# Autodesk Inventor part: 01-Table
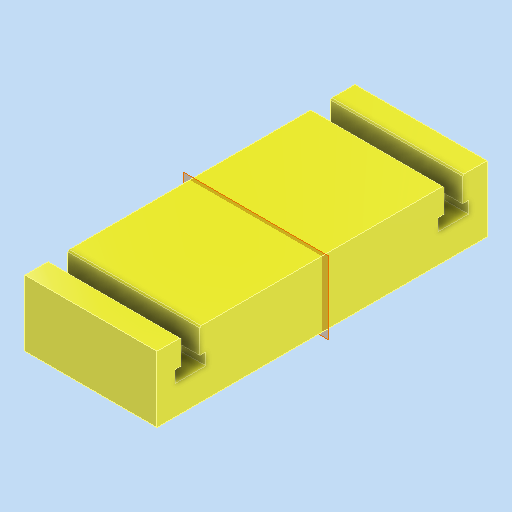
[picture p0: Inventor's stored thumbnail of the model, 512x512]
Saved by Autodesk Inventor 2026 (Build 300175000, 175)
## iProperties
Created: 2025-12
Part Number: 01-Table
Material: Générique
Document SubType Name: Modeling
Designer: thierry.jost
Density: 1 g/cm^3
Appearance: Jaune
Author: thierry.jost
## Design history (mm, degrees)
sketch "Esquisse1"
  geometry: L1 (25.468, 125)-(-24.532, 125); L2 (-24.532, 125)-(-24.532, -125); L3 (-24.532, -125)-(25.468, -125); L4 (25.468, -125)-(25.468, 125); 1 further point
  constraints: 8 end point, 2 parallel, 1 horizontal, 1 perpendicular
  dimensions: "d0" = 250 distance of L3.end L1.start; "d1" = 50 distance of L1.start L1.end; "d13" = 125 distance from line of L1 point (0, 0) (= 0.5 x d0)
extrude "Extrusion1" new body sketch "Esquisse1" distance "d2" = 100; taper "d3" = 0 deg
sketch "Esquisse2"
  geometry: L1 (-88, 6.468)-(-88, -2.532); L2 (-88, -2.532)-(-111, -2.532); L3 (-111, -2.532)-(-111, 6.468); L4 (-106.5, 58.725)-(-92.5, 58.725); L5 (-92.5, 58.725)-(-92.5, 6.468); L6 (-106.5, 6.468)-(-106.5, 58.725); L7 (-111, 6.468)-(-106.5, 6.468); L8 (-92.5, 6.468)-(-88, 6.468); L9 (125, 25.468)-(-125, 25.468) reference; 2 further points
  constraints: 16 end point, 4 parallel, 3 horizontal, 3 perpendicular, 1 midpoint
  dimensions: "d4" = 14 distance of L4.start L4.end; "d5" = 23 distance of L1.end L2.end; "d6" = 4.5 distance between parallel lines of L3 L6; "d7" = 9 distance of L2.end L3.end; "d8" = 99.5 horizontal distance of point (-99.5, 58.725) point (0, 0); "d9" = 19 distance between parallel lines of L9 L7; "d10" = 19 distance between parallel lines of L8 L9 (= d9)
extrude "Extrusion2" cut sketch "Esquisse2" extent not by distance; stored distance "d11" = 0; taper "d12" = 0 deg
fillet "Congé1" dims "d14" = 0.6
chamfer "Chanfrein1" distance "d15" = 1; stored, may be unused: second distance "d16" = 2, angle "d17" = 45 deg
mirror "Mise en miroir1"
node "Solide1"
